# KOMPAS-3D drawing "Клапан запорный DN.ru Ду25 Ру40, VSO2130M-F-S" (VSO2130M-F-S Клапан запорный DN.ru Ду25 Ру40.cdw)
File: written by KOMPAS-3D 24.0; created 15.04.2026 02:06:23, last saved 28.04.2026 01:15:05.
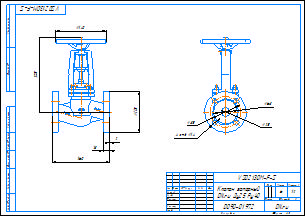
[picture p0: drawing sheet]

Document properties: Автор: DN.ru; Форматы листов документа: A3; Полное имя файла: VSO2130M-F-S Клапан запорный DN.ru Ду25 Ру40.m3d; Масса: 6; Наименование: Клапан запорный DN.ru Ду25 Ру40; Количество листов документа: 1; Примечание: D090-01972

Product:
- Part/product: Клапан запорный DN.ru Ду25 Ру40  | designation VSO2130M-F-S
    Масса: 6
    Раздел спецификации: Прочие изделия
    Примечание: D090-01972

Views: Вид 1, Вид:1, Проекционный вид 2
Referenced files in C:\Работа\VSO2130M-F-S Клапан запорный DN.ru\DN20\: VSO2130M-F-S DN20 PN40  Клапан запорный сильфонный DN.ru.m3d
Referenced files in C:\Работа\VSO2130M-F-S Клапан запорный DN.ru\DN25\: VSO2130M-F-S Клапан запорный DN.ru Ду25 Ру40.m3d
Referenced files in C:\Program Files\ASCON\KOMPAS-3D v24\Templates\: Чертеж_DN.ru.cdt
Referenced files in C:\Работа\ГОТОВЫЕ ИСХОДНИКИ\VSO2130M-F-S Клапан запорный сильфонный DN.ru Ду15-100 Ру40\DN25\: VSO2130M-F-S Клапан запорный DN.ru Ду25 Ру40.m3d
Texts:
  VSO2130M-F-S
  Чертеж_DN.ru.cdt
  Клапан запорный
  DN.ru Ду25 Ру40
  Клапан запорный DN.ru Ду25 Ру40
  VSO2130M-F-S  Клапан запорный DN.ru Ду25 Ру40
Dimensions and other numbers on the sheet: 0; 3; 2; 4; 115; 18; 205; 140; 160; 1; 5; 25; 68; 85; 4 отв.; 14; 1:2; 6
